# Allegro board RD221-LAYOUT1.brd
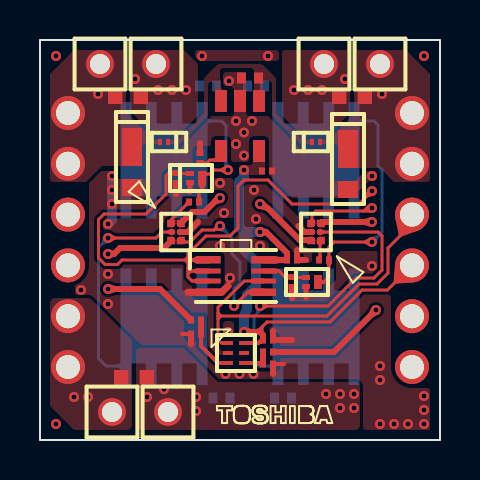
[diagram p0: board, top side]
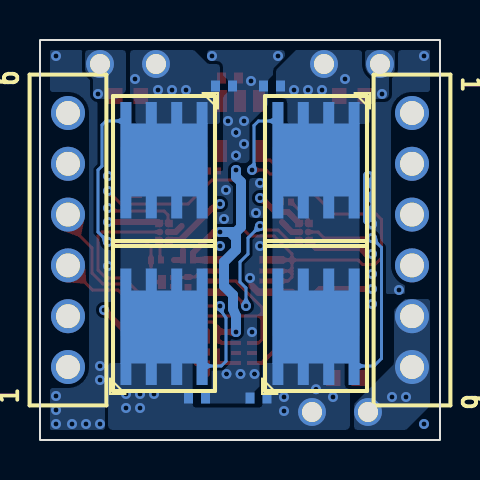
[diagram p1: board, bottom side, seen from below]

Outline 20 x 20 mm; copper layers: TOP, CONDUCTIVE2, CONDUCTIVE3, BOTTOM. Coordinates in mm from the lower left corner of the outline.
Outline path: rectangle 0,0 20,20

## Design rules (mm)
constraint set DEFAULT: 

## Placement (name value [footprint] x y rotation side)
C101  -  [KC00051KD]  10.5 18.1 180 top
C102  -  [KC00540KD]  8 14.1 90 top
C103  -  [KC00540KD]  11.35 13.45 0 top
C104  -  [KC00051KD]  8.4 17.7 0 bottom
C105  -  [KC00051KD]  9.07 2.1 0 bottom
C106  -  [KC00540KD]  11.4 5 0 top
C107  -  [KC00051KD]  10.8 17.7 180 bottom
C108  -  [KC00051KD]  12.15 2.1 180 bottom
C109  -  [KC00540KD]  12.6 9 0 top
CN101  -  [CU12000TD]  1.4 16.35 270 bottom
CN102  -  [CU12000TD]  18.6 3.65 90 bottom
D101  -  [MM02020KD]  4.6 13.9 90 top
D102  -  [MM02020KD]  15.4 13.8 90 top
D103  -  [KC10480CD]  6.2 14.9 0 top
D104  -  [KC10480CD]  13.8 14.9 180 top
DP101  -  [DP002X0KD]  3 18.8 0 top
DP102  -  [DP002X0KD]  5.8 18.8 0 top
DP103  -  [DP002X0KD]  17 18.8 0 top
DP104  -  [DP002X0KD]  14.2 18.8 0 top
DP105  -  [DP002X0KD]  6.4 1.4 0 top
DP106  -  [DP002X0KD]  3.6 1.4 0 top
IC101  -  [MM00631KD]  10 15.7 180 top
IC102  -  [DIC8T60KD]  9.8 8.2 270 top
IC103  -  [LA10251KD]  9.8 4.35 270 top
IC104  -  [BA10620KD]  6.8 10.4 270 top
IC105  -  [BA10620KD]  13.8 10.4 90 top
JP101  -  [KC00081KD]  4.4 17.2 0 top
JP102  -  [KC00081KD]  15.6 17.2 180 top
JP103  -  [KC00081KD]  4.7 3.1 180 top
NOREF  -  []  8 0 0 top
Q101  -  [LA10710KD]  7.8 13.1 0 top
Q102  -  [LA10710KD]  13.6 7.9 0 top
Q103  -  [SN10261KD]  6.2 13.45 0 bottom
Q104  -  [SN10261KD]  6.2 6.2 180 bottom
Q105  -  [SN10261KD]  13.8 13.45 0 bottom
Q106  -  [SN10261KD]  13.8 6.2 180 bottom
R101  -  [KC00540KD]  7.8 6 0 top
R102  -  [KC00540KD]  7.8 5.3 180 top
R103  -  [KC00540KD]  11.4 4.4 180 top
R104  -  [KC00540KD]  11.4 3.8 0 top
R105  -  [KC00540KD]  7.7 11.9 180 top
R106  -  [KC00540KD]  14.2 9 180 top
R107  -  [KC00540KD]  6.8 13.1 270 top
R108  -  [KC00540KD]  12.6 7.9 270 top

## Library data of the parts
C101 C104 C105 C107 C108 = DP0000016125
C102 C103 = DP0007093000
C106 C109 = DP0000015403
CN101 CN102 = DP0010563000
D101 = DP0010557000
D102 = DP0010558000
D103 D104 = DP0010560000
DP101-DP106 = DP9000817000
IC101 = DP0010559000
IC102 = DP0001429000
IC103 = DP0010561000
IC104 = DP0010555000
IC105 = DP0010556000
JP101-JP103 = DP0001376000
Q101 = DP0010564000
Q102 = DP0010513000
Q103-Q106 = DP0010562000
R101 = DP0000151164
R102 = DP0000151152
R103 R104 = DP0000152120
R105 R106 = DP0000155124
R107 R108 = DP0002867000

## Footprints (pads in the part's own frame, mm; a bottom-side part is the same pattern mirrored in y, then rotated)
BA10620KD
  round 0.325 smd: A1(-0.4,-0.2) A2(-0.4,0.2) B1(0,-0.2) B2(0,0.2) C1(0.4,-0.2) C2(0.4,0.2)
CU12000TD
  round 1.7 hole 1.2: 1(0,0) 2(2.54,0) 3(5.08,0) 4(7.62,0) 5(10.16,0) 6(12.7,0)
DIC8T60KD
  rect 0.375x1.24 smd: 1(-0.812,-1.385) 4(0.812,-1.385) 5(0.812,1.385) 8(-0.812,1.385)
  rect 0.25x1.24 smd: 2(-0.25,-1.385) 3(0.25,-1.385) 6(0.25,1.385) 7(-0.25,1.385)
DP002X0KD
  round 1.397 hole 1: 1(0,0)
KC00051KD
  rect 0.45x0.55 smd: 1(-0.425,0) 2(0.425,0)
KC00081KD
  rect 0.72x0.8 smd: 1(-0.64,0) 2(0.64,0)
KC00540KD
  rect 0.3x0.35 smd: 1(-0.25,0) 2(0.25,0)
KC10480CD
  rect 0.21x0.32 smd: A(-0.205,0) C(0.205,0)
LA10251KD
  rect 0.2x0.5 smd: 1(-0.5,-0.4) 2(0,-0.4) 3(0.5,-0.4) 4(0.5,0.4) 5(0,0.4) 6(-0.5,0.4)
LA10710KD
  rect 0.4x0.7 smd: D(0.3,0)
  rect 0.4x0.25 smd: G(-0.3,0.225) S(-0.3,-0.225)
MM00631KD
  rect 0.6x1.1 smd: 1(-0.95,-1.25) 2(0,-1.25) 3(0.95,-1.25) 4(0.95,1.25) 5(-0.95,1.25)
MM02020KD
  rect 0.85x1 smd: A(-1.275,0)
  rect 1.9x1 smd: C(0.75,0)
SN10261KD
  rect 0.55x1.1 smd: 1(-1.905,-2.9) 2(-0.635,-2.9) 3(0.635,-2.9) 4(1.905,-2.9)
  custom 1.09x1.09 smd: 5(0,0)

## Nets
GND: C101.2 C102.2 C103.2 C104.2 C105.2 C106.2 C107.2 C108.2 C109.2 CN101.3 CN101.4 D101.A D102.A IC101.2 IC102.4 IC103.2 IC104.B2 IC105.B2 Q101.S Q102.S R102.2 R104.2 R107.2 R108.2
VINA: CN101.1 CN101.2 D101.C D103.A DP101.1 JP101.1 R101.1
VINB: CN102.5 CN102.6 D102.C D104.A DP103.1 JP102.1 R103.1
EN20V: CN102.1 IC102.1 IC102.2 IC102.3 Q101.G R107.1
FLAG: CN102.4 IC102.6 IC103.1
LDO-VOUT: C103.1 C106.1 C109.1 CN102.3 IC101.5 IC102.8 IC103.6
SIG136: C101.1 D103.C D104.C IC101.1 IC101.3
SIG137: IC103.3 R101.2 R102.1
SIG141: IC103.4 R103.2 R104.1
SIG143: C104.1 DP102.1 IC104.A2 JP101.2 Q103.1 Q103.2 Q103.3
SIG144: Q103.5 Q104.5
SIG145: Q101.D Q103.4 R105.1
SIG146: IC104.A1 R105.2
SIG147: IC104.B1 Q104.4
SIG154: IC105.B1 Q106.4
SIG155: IC105.A1 R106.2
SIG156: C105.1 C108.1 DP105.1 IC104.C1 IC105.C1 JP103.1 Q104.1 Q104.2 Q104.3 Q106.1 Q106.2 Q106.3
SIG157: C107.1 DP104.1 IC105.A2 JP102.2 Q105.1 Q105.2 Q105.3
SIG168: C102.1 IC101.4
SIG170: IC102.5 IC104.C2
SIG171: IC102.7 Q102.G R108.1
SIG188: Q102.D Q105.4 R106.1
SIG190: Q105.5 Q106.5
VCT5V: CN102.2 IC105.C2
VOUT: CN101.5 CN101.6 DP106.1 JP103.2

Pads without a net: IC103 5

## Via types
v1: diameter 0.5, hole 0.25, TOP to BOTTOM, 77 vias

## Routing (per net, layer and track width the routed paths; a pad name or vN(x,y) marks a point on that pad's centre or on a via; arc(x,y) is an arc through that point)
GND: length 22.1
  TOP w0.2: 12.2,3.8 R104.2 ; R102.2 7.1,5.3
  TOP w0.25: Q102.S 13.3,7.1 ; Q101.S 7.5,12.4
  TOP w0.3: R107.2 6.8,12.3 ; R108.2 12.6,7.1 ; C102.2 8,14.85 ; 13.3,9 C109.2 12.85,9.49 ; IC104.B2 7.4,10.4 7.9,10.9 ; R102.2 7.55,4.8 ; 12.6,5 C106.2 11.65,5.45 ; 12.92,10.7 13.22,10.4 IC105.B2 ; R104.2 11.65,3.3
  TOP w0.35: 9.41,7.71 9.09,7.39 IC102.4 7.4,7.39
  CONDUCTIVE2 w0.15: 3.35,0.57 3.9,0.57 ; 6.15,0.57 6.67,0.57
  CONDUCTIVE2 w1: 1.4,12.45 CN101.3 ; CN101.3 2.5,11.27 ; CN101.3 CN101.4 ; CN101.4 2.4,8.73 ; CN101.4 1.4,7.55
  CONDUCTIVE3 w0.15: 6.17,0.57 6.62,0.57
  BOTTOM w0.5: v1(3.6,13.2) v1(3.6,12.5) v1(3.6,11.8) 3.6,11 v1(3.4,10.8)
  vias: v1(0.8,19.2) v1(0.8,0.8) v1(2.05,7.5) v1(3.4,8.3) v1(3.4,6.8) v1(8.1,19.2) v1(9,12.85) v1(9,9.7) v1(9.2,11.35) v1(9.28,3.3) v1(9.45,17.95) v1(9.4,5.4) v1(9.5,8.1) v1(9.8,15.95) v1(9.8,14.8) v1(9.97,3.3) v1(10.2,15.38) v1(10.2,14.22) v1(10.6,15.95) v1(10.7,12.5) v1(10.68,3.3) v1(10.8,11.05) v1(11,9.7) v1(11.4,19.2) v1(16.6,13.2) v1(16.6,8.7) v1(17,3.7) v1(17,3) v1(17,0.8) v1(17.7,0.8) v1(18.4,0.8) v1(19.2,19.2) v1(19.2,2.2) v1(19.2,1.5) v1(19.2,0.8)
VINA: length 15.2
  TOP w0.3: R101.1 6,7.55 v1(3.4,7.55)
  CONDUCTIVE3 w0.6: v1(3.4,7.55) 3.05,7.55 2.65,7.95 2.65,17.05 v1(2.9,17.3)
VINB: length 17.2
  TOP w0.3: R103.1 14.7,4.4 v1(16.8,6.5)
  CONDUCTIVE3 w0.6: v1(16.8,6.5) 17,6.5 17.35,6.85 17.35,16.79 v1(17.1,17.3)
EN20V: length 41.3
  TOP w0.15: 7.55,9 7.4,8.85 ; 7.55,9 7.4,9.15 ; 7.55,9 7.87,9 ; 7.55,9 7.4,9 ; 7.4,8.85 7.4,9 ; 7.4,8.85 7.25,9 ; 7.4,8.85 7.4,8.6 ; 7.4,9.15 7.25,9 ; 7.4,9.15 7.4,9 ; 7.4,9.15 7.4,9.3 8.3,10.2 9.5,10.2 9.9,10.6 9.9,12.7 10.2,13 11.4,13 12.6,11.8 15.95,11.8 v1(16.6,12.45) ; 7.25,9 7.4,9 ; 7.25,9 4.1,9 3.88,8.78 3.25,8.78 2.92,9.1 2.92,11.03 3.2,11.3 5.3,11.3 6.3,12.3 6.3,13.2 6.45,13.35 R107.1 7.1,13.32 7.42,13.32 ; 7.83,7.95 7.6,7.95 7.4,8.15 7.4,8.3 ; 7.4,8.45 7.4,8.6 ; 7.4,8.45 7.4,8.3 ; 7.4,8.45 7.55,8.45 ; 7.4,8.6 7.55,8.45 ; 7.55,8.45 7.4,8.3 ; 7.55,8.45 7.83,8.45
  TOP w0.25: IC102.3 7.83,7.95 ; 7.83,8.45 IC102.2 ; Q101.G 7.42,13.32
  TOP w0.35: 7.87,9 8.4,9
  CONDUCTIVE2 w0.15: v1(16.6,12.45) 16.05,11.9 16.05,10.75 16.4,10.4 16.8,10.4 17.3,9.9 17.3,4.95 CN102.1
FLAG: length 18.2
  TOP w0.15: 8.9,6.2 8.9,6.35 ; 8.9,6.2 9.05,6.2 ; 8.9,6.2 8.9,6.05 ; 8.9,6.35 9.05,6.2 ; 8.9,6.35 8.9,6.63 10.22,7.95 10.69,7.95 ; 8.9,6.05 8.9,5.03 9.07,4.85 9.25,4.85 ; 8.9,6.05 9.05,6.2 ; 9.05,6.2 14.35,6.2 15.95,7.8 16.85,7.8 17.4,8.35 17.4,9.6 18,10.2 CN102.4
  TOP w0.2: 9.25,4.85 IC103.1
  TOP w0.25: IC102.6 10.69,7.95
LDO-VOUT: length 24.9
  TOP w0.15: 11.1,5.65 11.35,5.9 14.5,5.9 16.1,7.5 17.37,7.5 CN102.3 ; 11.1,5.65 10.85,5.4 ; 11.1,5.65 11.1,5.4
  TOP w0.2: IC103.6 10.9,4.85 C106.1
  TOP w0.3: C106.1 11.15,5.25 11,5.4 v1(10.2,5.4) ; v1(11,10.4) 11.31,10.4 12.35,9.36 C109.1 11.79,9
  TOP w0.35: 11.79,9 11.19,9
  BOTTOM w0.5: v1(10.2,5.4) 10.2,6.2 10.35,6.55 10.35,7.25 10.8,7.7 10.8,8.9 10.2,9.5 10.2,10.1 ; 10.2,10.4 9.95,10.65 9.95,12.9 10.2,13.15 v1(10.2,13.5) ; 10.2,10.4 10.2,10.1 ; 10.2,10.4 10.5,10.4 ; 10.2,10.1 10.5,10.4 ; 10.5,10.4 v1(11,10.4)
SIG137: length 3
  TOP w0.2: IC103.3 8.9,3.85 8.05,4.7 R102.1
  TOP w0.3: R102.1 R101.2
SIG141: length 1.6
  TOP w0.2: IC103.4 10.9,3.85 R104.1
  TOP w0.3: R103.2 R104.1
SIG143: length 8.9
  TOP w0.3: v1(9,12.1) 8.74,11.92 8.22,11.4 7.6,11.4 IC104.A2
  CONDUCTIVE3 w0.6: v1(9,12.1) 8.6,12.1 8.2,12.5 8.2,16.6 v1(7.3,17.5)
  vias: v1(4.75,18.05) v1(5.9,17.5) v1(6.6,17.5)
SIG145: length 6.2
  TOP w0.15: 8.1,12.84 8.1,12.5 7.95,12.35 7.95,11.99 ; 8.1,13.3 8.5,13.3 8.7,13.5 v1(9.4,13.5)
  TOP w0.3: R105.1 7.95,11.99
  TOP w0.4: 8.1,12.84 Q101.D
  BOTTOM w0.15: v1(9.4,13.5) 9.3,13.8 9.3,15.72 9.07,15.95 8.33,15.95
  BOTTOM w0.3: 8.11,15.95 8.33,15.95
SIG146: length 1.5
  TOP w0.15: IC104.A1 6.6,11.05 R105.2
SIG147: length 11.1
  TOP w0.15: IC104.B1 6.1,10.4 5.8,10.1 v1(3.4,10.1)
  BOTTOM w0.15: v1(3.4,10.1) 2.92,9.62 2.92,4.08 3.3,3.7 4.07,3.7
  BOTTOM w0.3: 4.07,3.7 4.29,3.7
SIG154: length 15.9
  TOP w0.15: IC105.B1 16.9,10.4 17.1,10.2 17.1,8.5 16.7,8.1 15.8,8.1 14.4,6.7 v1(11,6.7)
  BOTTOM w0.15: 11.67,3.7 10.94,3.7 10.7,3.94 10.7,6.1 10.9,6.4 v1(11,6.7)
  BOTTOM w0.3: 11.67,3.7 11.89,3.7
SIG155: length 1
  TOP w0.15: R106.2 14,9.2 IC105.A1
SIG156: length 28.1
  TOP w0.3: IC105.C1 14.1,10.9 v1(16.6,10.9) ; IC104.C1 6.2,9.6 4,9.6 3.7,9.3 v1(3.4,9.3)
  CONDUCTIVE3 w0.5: 5.35,8.35 5.9,8.9 ; 5.35,8.35 5.35,9.1 ; 5.35,8.35 v1(5.35,2.15) ; 5.9,8.9 11.3,8.9 13.3,10.9 v1(16.6,10.9) ; 5.9,8.9 5.55,8.9 5.35,9.1 ; 5.35,9.1 5.15,9.3 v1(3.4,9.3)
  vias: v1(6.2,2.54) v1(7.8,2.15) v1(7.8,1.45) v1(14.3,2.3) v1(15,2.3) v1(15,1.6) v1(15.7,2.3) v1(15.7,1.6)
SIG157: length 9.9
  TOP w0.3: v1(11,11.8) 11.4,11.58 12.98,10 IC105.A2
  CONDUCTIVE3 w0.6: v1(11,11.8) 11.3,11.8 11.9,12.4 11.9,16.7 v1(12.7,17.5)
  vias: v1(13.4,17.5) v1(14.1,17.5) v1(15.25,18.05)
SIG168: length 1.1
  TOP w0.15: 8.77,14 8.5,14 8.35,13.85 8.02,13.85
  TOP w0.2: 8.77,14 9,14
  TOP w0.3: C102.1 8.02,13.85
SIG170: length 8.6
  TOP w0.15: v1(9,10.7) 8.7,10.5 8.1,10.5 7.5,9.9 7.25,9.9 IC104.C2 ; v1(9.7,6.7) 10.39,7.39 10.65,7.39
  TOP w0.37: 10.65,7.39 IC102.5
  BOTTOM w0.15: v1(9.7,6.7) 9.7,7.6 10,7.9 10,8.9 9.6,9.3 9.6,10.1 v1(9,10.7)
SIG171: length 2.2
  TOP w0.15: 11.77,8.45 11.95,8.45 12.25,8.15 R108.1 12.9,8.12 13.22,8.12
  TOP w0.25: 11.77,8.45 IC102.7 ; Q102.G 13.22,8.12
SIG188: length 11.8
  TOP w0.15: 14.45,8.9 14.45,8.15 14.2,7.9 Q102.D ; v1(16.6,9.9) 14.7,9.9 14.45,9.65 14.45,9.02
  TOP w0.3: 14.45,9.02 R106.1 14.45,8.9
  BOTTOM w0.15: 15.93,15.95 16.7,15.95 16.9,15.75 16.9,13.7 17.1,13.5 17.1,10.4 v1(16.6,9.9)
  BOTTOM w0.3: 15.71,15.95 15.93,15.95
VCT5V: length 10.3
  TOP w0.15: 16.2,11.45 16.35,11.6 v1(16.6,11.6) 16.45,11.45 16.2,11.45 ; 16.2,11.45 13.8,11.45 13.6,11.25 IC105.C2
  CONDUCTIVE2 w0.15: CN102.2 17.65,7.14 17.65,10.55 v1(16.6,11.6)
VOUT:
  vias: v1(1.7,2.15) v1(2.4,2.15)

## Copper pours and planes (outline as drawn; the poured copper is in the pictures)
GND on TOP: outline of 88 points within 7.93,7.4 13.6,12.78
GND on TOP: 8.02,18.95 7.92,18.99 7.79,19.12 7.75,19.22 7.75,19.35 7.79,19.46 7.9,19.5 11.8,19.5 11.91,19.46 11.95,19.35 11.95,19.1 11.91,18.99 11.8,18.95
GND on TOP: outline of 294 points within 1.74,0.5 19.5,18.4
GND on TOP: 3.79,10.35 3.77,10.35 3.75,10.36 3.5,10.49 3.4,10.5 3.3,10.5 3.19,10.54 3.15,10.65 3.15,10.9 3.16,10.93 3.17,10.95 3.27,11.05 3.3,11.07 3.32,11.07 5.3,11.07 5.39,11.09 5.46,11.14 6.46,12.14 6.52,12.24 6.53,12.3 6.53,12.35 6.57,12.46 6.67,12.5 7.55,12.5 7.6,12.48 7.62,12.43 7.62,12.35 7.6,12.3 7.55,12.28 7.33,12.28 7.17,12.21 7.1,12.05 7.1,11.9 7.09,11.87 7.08,11.85 6.44,11.21 6.4,11.17 6.38,11.16 6.26,11.08 6.21,10.94 6.21,10.91 6.2,10.89 6.19,10.86 5.7,10.37 5.67,10.36 5.64,10.35
GND on TOP: 7.44,10.25 7.38,10.27 7.36,10.33 7.36,10.58 7.38,10.64 7.39,10.67 7.4,10.7 7.42,10.72 7.51,10.79 7.8,11.08 7.83,11.09 7.86,11.1 8.22,11.1 8.34,11.12 8.43,11.19 8.89,11.64 8.92,11.66 9.11,11.71 9.4,12.15 9,12.5 8.75,12.5 8.64,12.54 8.6,12.65 8.6,12.89 8.61,12.95 8.64,12.99 8.71,13.06 8.81,13.1 9.53,13.1 9.63,13.06 9.68,12.95 9.68,11.19 9.67,11.16 9.65,11.14 9.6,11.11 9.55,11.1 9,11.1 8.8,11.05 8.65,10.9 8.62,10.82 8.6,10.78 8.58,10.74 8.53,10.72 8.1,10.72 8.01,10.71 7.94,10.66 7.58,10.3 7.53,10.26 7.47,10.25
GND on BOTTOM: 10.43,10.8 10.37,10.82 10.35,10.88 10.35,12.65 10.36,12.68 10.37,12.71 10.48,12.82 10.57,12.95 10.6,13.1 10.6,13.5 10.41,13.84 10.02,13.86 9.98,13.85 9.74,13.85 9.68,13.86 9.63,13.89 9.57,13.96 9.54,14 9.53,14.06 9.53,15.58 9.53,15.72 9.51,15.81 9.46,15.88 8.64,16.7 8.61,16.74 8.6,16.93 8.6,17.94 8.56,18.04 8.37,18.23 8.36,18.25 8.35,18.28 8.35,18.44 8.31,18.59 8.26,18.65 7.79,19.12 7.75,19.22 7.75,19.35 7.79,19.46 7.9,19.5 11.5,19.5 11.61,19.46 11.65,19.35 11.65,19.16 11.61,19.06 11.54,18.99 11.44,18.95 11.15,18.95 11,18.91 10.89,18.8 10.85,18.65 10.85,18.28 10.84,18.25 10.83,18.23 10.64,18.04 10.6,17.94 10.6,17.46 10.61,17.4 10.64,17.36 10.81,17.19 10.84,17.15 10.85,13.53 10.87,13.47 10.93,13.45 11.18,13.45 11.23,13.43 11.25,13.38 11.25,12.35 11.21,12.24 11.1,12.2 11,12.2 10.6,11.8 11,11.4 11.1,11.4 11.21,11.36 11.25,11.25 11.25,10.95 11.21,10.84 11.1,10.8
GND on BOTTOM: 8.9,11.1 8.79,11.14 8.75,11.25 8.75,11.55 8.79,11.66 8.9,11.7 9,11.7 9.28,11.82 9.4,12.1 9.4,12.1 9.28,12.38 9,12.5 8.9,12.5 8.79,12.54 8.75,12.65 8.75,12.95 8.79,13.06 8.9,13.1 9.4,13.1 9.51,13.06 9.55,12.95 9.55,12.1 9.55,12.1 9.55,11.25 9.51,11.14 9.4,11.1
GND on BOTTOM: 16.9,0.5 16.79,0.54 16.75,0.65 16.75,6.03 16.77,6.08 16.82,6.1 17.2,6.51 16.8,6.9 16.5,6.9 16.39,6.94 16.35,7.05 16.35,9.34 16.39,9.44 16.41,9.46 16.51,9.5 16.6,9.5 16.84,9.58 16.99,9.79 17.04,10.01 17.06,10.05 17.26,10.24 17.31,10.31 17.32,10.4 17.32,13.5 17.31,13.59 17.26,13.66 17.15,13.77 17.13,13.8 17.12,13.82 17.13,16.84 17.14,16.88 17.41,17.05 17.5,17.3 17.5,17.96 17.51,17.99 17.52,18.01 17.81,18.3 17.88,18.4 17.9,18.51 17.9,19.35 17.89,19.41 17.91,19.47 17.97,19.5 19.43,19.5 19.48,19.48 19.5,19.43 19.5,17.55 19.46,17.44 19.35,17.4 18.6,17.4 17.86,17.09 17.55,16.35 17.55,3.65 17.86,2.91 18.6,2.6 19.35,2.6 19.46,2.56 19.5,2.45 19.5,0.57 19.48,0.52 19.43,0.5
GND on BOTTOM: 9.43,1.82 9.32,1.87 9.28,1.98 9.28,2.42 9.05,2.65 9.03,2.68 9.03,2.71 9.03,3.78 9.04,3.83 9.13,3.87 9.15,3.91 9.15,6.12 9.13,6.18 9.07,6.2 8.82,6.2 8.77,6.22 8.75,6.28 8.75,10.26 8.78,10.32 8.85,10.33 8.9,10.31 9.11,10.26 9.15,10.24 9.35,10.03 9.37,10 9.38,9.98 9.38,9.3 9.39,9.21 9.44,9.14 9.75,8.83 9.77,8.8 9.78,8.78 9.78,8.02 9.77,8 9.75,7.97 9.54,7.76 9.49,7.69 9.47,7.6 9.47,7.13 9.46,7.09 9.35,6.9 9.36,6.49 9.72,6.3 9.78,6.28 9.8,6.23 9.8,5.4 9.98,5.06 10.44,5.03 10.47,4.97 10.47,3.94 10.49,3.85 10.54,3.78 10.78,3.54 10.85,3.49 10.94,3.48 11.35,3.48 11.4,3.45 11.42,3.4 11.42,2.65 11.5,2.46 11.7,2.38 11.88,2.38 11.93,2.35 11.95,2.3 11.95,1.9 11.93,1.85 11.88,1.82
GND on BOTTOM: 1.83,7.3 1.78,7.32 1.75,7.38 1.75,7.69 1.77,7.73 1.8,7.76 2.28,8.15 2.45,8.75 2.45,11.25 2.45,11.29 2.45,13.79 2.45,13.83 2.45,16.33 2.15,17.09 1.4,17.4 0.65,17.4 0.54,17.44 0.5,17.55 0.5,19.43 0.52,19.48 0.57,19.5 1.95,19.5 2.06,19.46 2.1,19.35 2.1,18.51 2.14,18.36 2.19,18.3 2.38,18.11 2.39,18.09 2.4,18.06 2.4,17.3 2.52,17.02 2.8,16.9 3.17,16.9 3.23,16.88 3.25,16.82 3.25,13.53 3.27,13.47 3.33,13.45 3.58,13.45 3.63,13.43 3.65,13.38 3.65,10.65 3.61,10.54 3.5,10.5 3.4,10.5 3.16,10.42 3.01,10.2 2.96,9.99 2.94,9.95 2.77,9.78 2.72,9.71 2.7,9.62 2.7,7.38 2.68,7.32 2.62,7.3
GND on CONDUCTIVE2: outline of 160 points within 0.5,0.5 19.5,19.5 ; 22 cut-outs
GND on CONDUCTIVE3: outline of 114 points within 0.5,0.5 19.5,10.5 ; 6 cut-outs
GND on CONDUCTIVE3: outline of 101 points within 0.5,9.3 19.5,19.5 ; 7 cut-outs
VINA on BOTTOM: 2.8,17.05 2.62,17.12 2.55,17.3 2.55,18.09 2.51,18.19 2.29,18.41 2.25,18.51 2.25,19.35 2.29,19.46 2.4,19.5 3.6,19.5 3.7,19.47 3.75,19.38 3.75,19.35 3.75,18.8 3.67,18.46 3.37,18.12 3.35,18.01 3.35,17.2 3.31,17.09 3.2,17.05
VINB on BOTTOM: 16.16,17.05 16.06,17.09 15.74,17.41 15.7,17.51 15.7,19.35 15.74,19.46 15.85,19.5 17.6,19.5 17.71,19.46 17.75,19.35 17.75,18.51 17.71,18.41 17.39,18.09 17.35,17.99 17.35,17.3 17.32,17.18 17.23,17.08 17.1,17.05
LDO-VOUT on TOP: 10.1,13.25 9.99,13.29 9.95,13.4 9.95,13.6 9.99,13.71 10.1,13.75 10.49,13.75 10.55,13.76 10.59,13.79 10.61,13.81 10.65,13.91 10.65,14.75 10.69,14.86 10.8,14.9 11.1,14.9 11.21,14.86 11.25,14.75 11.25,13.4 11.21,13.29 11.1,13.25
SIG136 on TOP: 6.38,14.8 6.32,14.82 6.3,14.88 6.3,14.93 6.32,14.98 6.38,15 6.83,15 6.88,15.01 6.93,15.04 8.16,16.27 8.19,16.32 8.2,16.37 8.2,18.04 8.24,18.14 8.86,18.76 8.96,18.8 11.04,18.8 11.14,18.76 11.76,18.14 11.8,18.04 11.8,16.37 11.81,16.32 11.84,16.27 13.12,15.01 13.17,15 13.62,15 13.68,14.98 13.7,14.93 13.7,14.88 13.68,14.82 13.62,14.8 13.06,14.8 13,14.81 12.96,14.84 11.64,16.16 11.61,16.2 11.6,16.26 11.6,17.8 11.56,17.91 11.45,17.95 11.3,17.95 11.19,17.91 11.15,17.8 11.15,16.79 11.12,16.72 11.05,16.69 10.8,16.69 10.73,16.72 10.7,16.79 10.7,18.45 10.66,18.56 10.55,18.6 9.15,18.6 9.04,18.56 9,18.45 9,17.71 9.01,17.65 9.04,17.61 9.31,17.34 9.34,17.3 9.35,17.24 9.35,16.77 9.33,16.72 9.28,16.7 8.82,16.7 8.77,16.72 8.75,16.77 8.75,17.75 8.71,17.86 8.6,17.9 8.55,17.9 8.44,17.86 8.4,17.75 8.4,16.26 8.39,16.2 8.36,16.16 7.04,14.84 7,14.81 6.94,14.8
SIG143 on TOP: 4.54,16.41 4.51,16.45 4.5,16.51 4.5,19.35 4.54,19.46 4.65,19.5 7.14,19.5 7.24,19.46 7.86,18.84 7.9,18.74 7.9,16.26 7.89,16.23 7.88,16.2 7.05,15.37 7.02,15.36 6.99,15.35 5.66,15.35 5.6,15.36 5.56,15.39
SIG143 on BOTTOM: 3.65,15.8 3.54,15.84 3.5,15.95 3.5,18.01 3.51,18.05 3.8,18.39 3.9,18.8 3.9,19.35 3.94,19.46 4.05,19.5 7.17,19.5 7.2,19.49 7.22,19.48 8.16,18.54 8.2,18.44 8.2,17.25 8.16,17.14 8.05,17.1 7.91,17.1 7.77,17.06 7.67,16.96 7.63,16.82 7.63,15.95 7.59,15.84 7.48,15.8
SIG144 on BOTTOM: 4.17,5.1 4.07,5.14 4.03,5.25 4.03,14.6 4.07,14.71 4.17,14.75 8.22,14.75 8.33,14.71 8.38,14.6 8.38,5.25 8.33,5.14 8.22,5.1
SIG156 on TOP: 5.05,0.5 4.92,0.53 4.83,0.62 4.8,0.75 4.8,4.45 4.84,4.56 4.95,4.6 7.16,4.6 7.19,4.59 7.21,4.58 8.81,2.97 8.93,2.91 8.99,2.9 15.75,2.9 15.93,2.83 16,2.65 16,0.75 15.93,0.57 15.75,0.5
SIG156 on BOTTOM: 4.75,0.5 4.57,0.57 4.5,0.75 4.5,2.48 4.52,2.53 4.56,2.56 4.71,2.65 4.77,2.83 4.77,3.77 4.79,3.83 4.84,3.85 8.72,3.85 8.83,3.81 8.88,3.7 8.88,1.77 8.92,1.67 9.03,1.62 12.22,1.62 12.33,1.67 12.37,1.77 12.37,3.77 12.39,3.83 12.45,3.85 16.45,3.85 16.56,3.81 16.6,3.7 16.6,0.75 16.53,0.57 16.35,0.5
SIG156 on CONDUCTIVE3: 7.65,1.15 7.54,1.19 7.5,1.3 7.5,2.45 7.54,2.56 7.65,2.6 15.85,2.6 15.96,2.56 16,2.45 16,1.3 15.96,1.19 15.85,1.15
SIG157 on TOP: 13.01,15.35 12.98,15.36 12.95,15.37 12.12,16.2 12.11,16.23 12.1,16.26 12.1,19.35 12.14,19.46 12.25,19.5 15.35,19.5 15.46,19.46 15.5,19.35 15.5,16.41 15.46,16.31 14.54,15.39 14.44,15.35
SIG157 on BOTTOM: 11.15,15.8 11.04,15.84 11,15.95 11,18.65 11.04,18.76 11.15,18.8 11.54,18.8 11.64,18.84 12.26,19.46 12.36,19.5 15.35,19.5 15.46,19.46 15.5,19.35 15.5,17.17 15.48,17.12 15.29,17 15.23,16.82 15.23,15.95 15.19,15.84 15.08,15.8
SIG190 on BOTTOM: 11.78,5.1 11.67,5.14 11.62,5.25 11.62,14.6 11.67,14.71 11.78,14.75 15.82,14.75 15.93,14.71 15.97,14.6 15.97,5.25 15.93,5.14 15.82,5.1
VOUT on BOTTOM: 1.8,0.5 1.71,0.52 1.63,0.57 0.57,1.63 0.52,1.71 0.5,1.8 0.5,6.9 0.54,7.01 0.65,7.05 1.69,7.05 1.75,7.04 1.79,7.01 2.26,6.54 2.3,6.44 2.3,3.9 2.33,3.78 2.37,3.73 4.26,1.84 4.3,1.74 4.3,0.65 4.26,0.54 4.15,0.5

Small or netless copper shapes (teardrops, artwork), in the pictures only: 65 on TOP, 10 on BOTTOM, 4 on CONDUCTIVE2, 3 on CONDUCTIVE3

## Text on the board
Ref Des/Silkscreen Bottom: 1 | 6
SYMBOL-2-TOP: IC101 | IC102 | IC103 | MUX1 | VINA | VOUT | D101 | GND | IC104 | D102 | IC105 | FLAG | VINB
SYMBOL-2-BOTTOM: 1 | Q104 | Q103 | Q106 | Q105
User.5: 1 | 6
